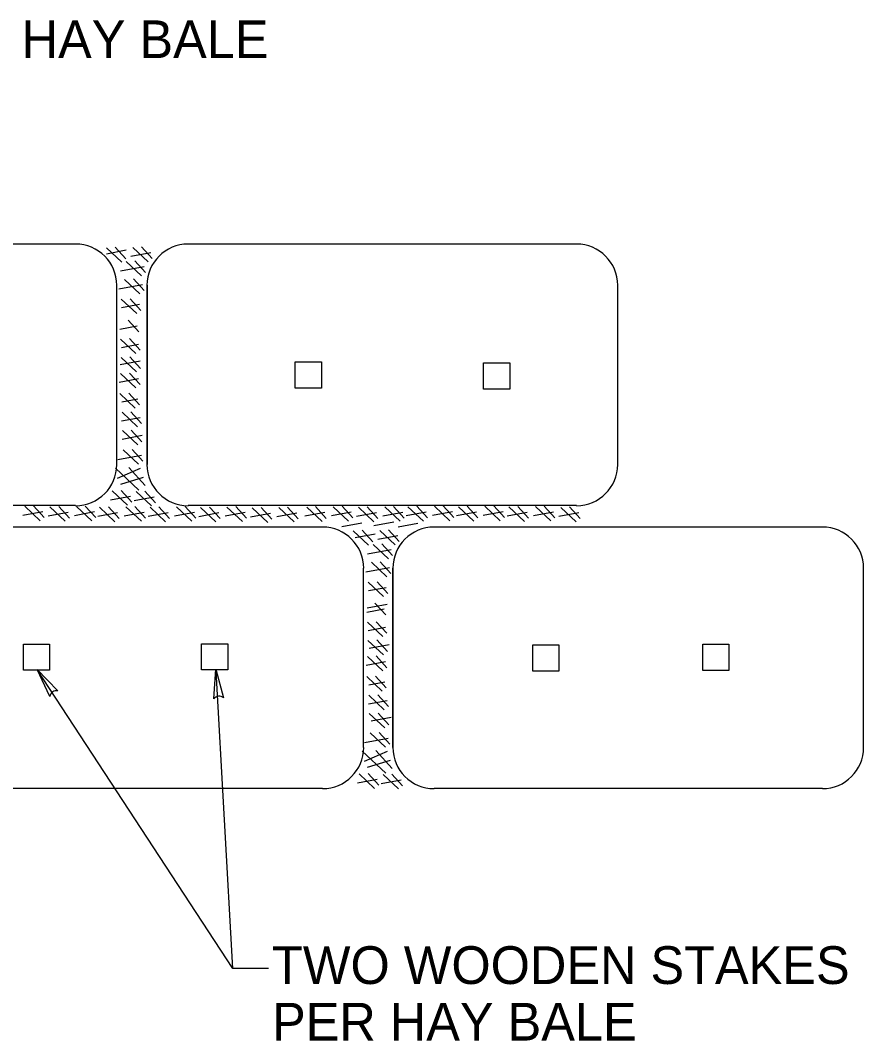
# Model space of a CAD drawing. Extents: x 0 to 2.83, y -0.06 to 1.83.
# Drawn here: x 2.1578 to 2.3533, y 0.8651 to 1.1016 of the extents above; entities that cross this region are included whole.
import ezdxf

# ---------------------------------------------------------------- set-up
doc = ezdxf.new("R2010")
doc.units = 0
for name, color, linetype in [('Edge_of_Truck_Apron', 7, 'Continuous'), ('Haybales', 7, 'Continuous'), ('Longitudinal Joint', 7, 'Continuous'), ('Wood Stakes', 7, 'Continuous')]:
    doc.layers.add(name, color=color, linetype=linetype)

msp = doc.modelspace()

# ---------------------------------------------------------------- linework, layer by layer
at = {"layer": 'Edge_of_Truck_Apron'}
for p, q in [((2.20708, 0.88183), (2.16174, 0.95101)), ((2.20708, 0.88183), (2.20318, 0.95078)), ((2.21533, 0.88183), (2.20708, 0.88183))]:
    msp.add_line(p, q, dxfattribs=at)
at = {"layer": 'Haybales'}
for p, q in [((2.17059, 1.04975), (2.08056, 1.04975)), ((2.17059, 1.04975), (2.08056, 1.04975)), ((2.17773, 1.04889), (2.1813, 1.04555)), ((2.17773, 1.04889), (2.1813, 1.04555)), ((2.18236, 1.04831), (2.17773, 1.04745)), ((2.18236, 1.04831), (2.17773, 1.04745)), ((2.17978, 1.04901), (2.18226, 1.0463)), ((2.17978, 1.04901), (2.18226, 1.0463)), ((2.18806, 1.04772), (2.18343, 1.04686)), ((2.18806, 1.04772), (2.18343, 1.04686)), ((2.18386, 1.04899), (2.18742, 1.04565)), ((2.18386, 1.04899), (2.18742, 1.04565)), ((2.18591, 1.0491), (2.18839, 1.0464)), ((2.18591, 1.0491), (2.18839, 1.0464)), ((2.28673, 1.04975), (2.1967, 1.04975)), ((2.28673, 1.04975), (2.1967, 1.04975)), ((2.1823, 1.04575), (2.18587, 1.04241)), ((2.1823, 1.04575), (2.18587, 1.04241)), ((2.18436, 1.04586), (2.18683, 1.04316)), ((2.18436, 1.04586), (2.18683, 1.04316)), ((2.1865, 1.04448), (2.18102, 1.04346)), ((2.1865, 1.04448), (2.18102, 1.04346)), ((2.18194, 1.04158), (2.18551, 1.03824)), ((2.18194, 1.04158), (2.18551, 1.03824)), ((2.18399, 1.04169), (2.18647, 1.03899)), ((2.18399, 1.04169), (2.18647, 1.03899)), ((2.18014, 0.99867), (2.18014, 1.0402)), ((2.18014, 0.99867), (2.18014, 1.0402)), ((2.18614, 1.04031), (2.18065, 1.03929)), ((2.18614, 1.04031), (2.18065, 1.03929)), ((2.18716, 1.0402), (2.18716, 0.99867)), ((2.18716, 0.99867), (2.18716, 1.0402)), ((2.18716, 1.0402), (2.18716, 0.99867)), ((2.18716, 0.99867), (2.18716, 1.0402)), ((2.29628, 0.99867), (2.29628, 1.0402)), ((2.29628, 0.99867), (2.29628, 1.0402)), ((2.1812, 1.03699), (2.18477, 1.03364)), ((2.1812, 1.03699), (2.18477, 1.03364)), ((2.18325, 1.0371), (2.18573, 1.03439)), ((2.18325, 1.0371), (2.18573, 1.03439)), ((2.1854, 1.03571), (2.18128, 1.03495)), ((2.1854, 1.03571), (2.18128, 1.03495)), ((2.18277, 1.03211), (2.18524, 1.02941)), ((2.18277, 1.03211), (2.18524, 1.02941)), ((2.18491, 1.03073), (2.18089, 1.02998)), ((2.18491, 1.03073), (2.18089, 1.02998)), ((2.18101, 1.02772), (2.18458, 1.02438)), ((2.18101, 1.02772), (2.18458, 1.02438)), ((2.18521, 1.02645), (2.18121, 1.02571)), ((2.18521, 1.02645), (2.18121, 1.02571)), ((2.18306, 1.02783), (2.18554, 1.02513)), ((2.18306, 1.02783), (2.18554, 1.02513)), ((2.18554, 1.02262), (2.18091, 1.02176)), ((2.18554, 1.02262), (2.18091, 1.02176)), ((2.18115, 1.0235), (2.18471, 1.02015)), ((2.18115, 1.0235), (2.18471, 1.02015)), ((2.1832, 1.02361), (2.18568, 1.0209)), ((2.1832, 1.02361), (2.18568, 1.0209)), ((2.18102, 1.01976), (2.18458, 1.01642)), ((2.18102, 1.01976), (2.18458, 1.01642)), ((2.18307, 1.01987), (2.18555, 1.01717)), ((2.18307, 1.01987), (2.18555, 1.01717)), ((2.18522, 1.01849), (2.18071, 1.01766)), ((2.18522, 1.01849), (2.18071, 1.01766)), ((2.18086, 1.01509), (2.18443, 1.01174)), ((2.18086, 1.01509), (2.18443, 1.01174)), ((2.18291, 1.0152), (2.18539, 1.01249)), ((2.18291, 1.0152), (2.18539, 1.01249)), ((2.18506, 1.01381), (2.18133, 1.01312)), ((2.18506, 1.01381), (2.18133, 1.01312)), ((2.18136, 1.01076), (2.18492, 1.00741)), ((2.18136, 1.01076), (2.18492, 1.00741)), ((2.18341, 1.01087), (2.18589, 1.00816)), ((2.18341, 1.01087), (2.18589, 1.00816)), ((2.18555, 1.00948), (2.18126, 1.00869)), ((2.18555, 1.00948), (2.18126, 1.00869)), ((2.18601, 1.00535), (2.18139, 1.00449)), ((2.18601, 1.00535), (2.18139, 1.00449)), ((2.18145, 1.00654), (2.18501, 1.0032)), ((2.18145, 1.00654), (2.18501, 1.0032)), ((2.1835, 1.00665), (2.18598, 1.00395)), ((2.1835, 1.00665), (2.18598, 1.00395)), ((2.18585, 1.00078), (2.18037, 0.99976)), ((2.18585, 1.00078), (2.18037, 0.99976)), ((2.18166, 1.00205), (2.18522, 0.99871)), ((2.18166, 1.00205), (2.18522, 0.99871)), ((2.18371, 1.00216), (2.18618, 0.99946)), ((2.18371, 1.00216), (2.18618, 0.99946)), ((2.18296, 0.99795), (2.18673, 0.99383)), ((2.18296, 0.99795), (2.18673, 0.99383)), ((2.17983, 0.99778), (2.18527, 0.99268)), ((2.17983, 0.99778), (2.18527, 0.99268)), ((2.18557, 0.99775), (2.18025, 0.99542)), ((2.18557, 0.99775), (2.18025, 0.99542)), ((2.18106, 0.99411), (2.18638, 0.99573)), ((2.18106, 0.99411), (2.18638, 0.99573)), ((2.1833, 0.99127), (2.17868, 0.99041)), ((2.1833, 0.99127), (2.17868, 0.99041)), ((2.17911, 0.99254), (2.18267, 0.9892)), ((2.17911, 0.99254), (2.18267, 0.9892)), ((2.18116, 0.99266), (2.18363, 0.98995)), ((2.18116, 0.99266), (2.18363, 0.98995)), ((2.18882, 0.99112), (2.1842, 0.99026)), ((2.18882, 0.99112), (2.1842, 0.99026)), ((2.18463, 0.99239), (2.18819, 0.98905)), ((2.18463, 0.99239), (2.18819, 0.98905)), ((2.18668, 0.9925), (2.18915, 0.9898)), ((2.18668, 0.9925), (2.18915, 0.9898)), ((2.15882, 0.98897), (2.16238, 0.98563)), ((2.15882, 0.98897), (2.16238, 0.98563)), ((2.16087, 0.98908), (2.16335, 0.98638)), ((2.16087, 0.98908), (2.16335, 0.98638)), ((2.16465, 0.98883), (2.16822, 0.98549)), ((2.16465, 0.98883), (2.16822, 0.98549)), ((2.16671, 0.98895), (2.16918, 0.98624)), ((2.16671, 0.98895), (2.16918, 0.98624)), ((2.17078, 0.98893), (2.17435, 0.98559)), ((2.17078, 0.98893), (2.17435, 0.98559)), ((2.17283, 0.98904), (2.17531, 0.98634)), ((2.17283, 0.98904), (2.17531, 0.98634)), ((2.17615, 0.98875), (2.17972, 0.9854)), ((2.17615, 0.98875), (2.17972, 0.9854)), ((2.1782, 0.98886), (2.18068, 0.98615)), ((2.1782, 0.98886), (2.18068, 0.98615)), ((2.18228, 0.98885), (2.18585, 0.9855)), ((2.18228, 0.98885), (2.18585, 0.9855)), ((2.18433, 0.98896), (2.18681, 0.98625)), ((2.18433, 0.98896), (2.18681, 0.98625)), ((2.18786, 0.98875), (2.19143, 0.98541)), ((2.18786, 0.98875), (2.19143, 0.98541)), ((2.18991, 0.98886), (2.19239, 0.98616)), ((2.18991, 0.98886), (2.19239, 0.98616)), ((2.19399, 0.98885), (2.19755, 0.9855)), ((2.19399, 0.98885), (2.19755, 0.9855)), ((2.19604, 0.98896), (2.19851, 0.98625)), ((2.19604, 0.98896), (2.19851, 0.98625)), ((2.19957, 0.9887), (2.20313, 0.98536)), ((2.19957, 0.9887), (2.20313, 0.98536)), ((2.20162, 0.98881), (2.2041, 0.98611)), ((2.20162, 0.98881), (2.2041, 0.98611)), ((2.2057, 0.9888), (2.20926, 0.98545)), ((2.2057, 0.9888), (2.20926, 0.98545)), ((2.20775, 0.98891), (2.21022, 0.9862)), ((2.20775, 0.98891), (2.21022, 0.9862)), ((2.21157, 0.9886), (2.21513, 0.98525)), ((2.21157, 0.9886), (2.21513, 0.98525)), ((2.21362, 0.98871), (2.2161, 0.986)), ((2.21362, 0.98871), (2.2161, 0.986)), ((2.2177, 0.9887), (2.22126, 0.98535)), ((2.2177, 0.9887), (2.22126, 0.98535)), ((2.21975, 0.98881), (2.22222, 0.9861)), ((2.21975, 0.98881), (2.22222, 0.9861)), ((2.22419, 0.98878), (2.22776, 0.98543)), ((2.22419, 0.98878), (2.22776, 0.98543)), ((2.22624, 0.98889), (2.22872, 0.98618)), ((2.22624, 0.98889), (2.22872, 0.98618)), ((2.23032, 0.98887), (2.23388, 0.98553)), ((2.23032, 0.98887), (2.23388, 0.98553)), ((2.23237, 0.98898), (2.23484, 0.98628)), ((2.23237, 0.98898), (2.23484, 0.98628)), ((2.23615, 0.98874), (2.23972, 0.98539)), ((2.23615, 0.98874), (2.23972, 0.98539)), ((2.2382, 0.98885), (2.24068, 0.98614)), ((2.2382, 0.98885), (2.24068, 0.98614)), ((2.24228, 0.98883), (2.24585, 0.98549)), ((2.24228, 0.98883), (2.24585, 0.98549)), ((2.24433, 0.98895), (2.24681, 0.98624)), ((2.24433, 0.98895), (2.24681, 0.98624)), ((2.24766, 0.98888), (2.25122, 0.98553)), ((2.24766, 0.98888), (2.25122, 0.98553)), ((2.24971, 0.98899), (2.25218, 0.98628)), ((2.24971, 0.98899), (2.25218, 0.98628)), ((2.25378, 0.98897), (2.25735, 0.98563)), ((2.25378, 0.98897), (2.25735, 0.98563)), ((2.25583, 0.98908), (2.25831, 0.98638)), ((2.25583, 0.98908), (2.25831, 0.98638)), ((2.25936, 0.98888), (2.26293, 0.98553)), ((2.25936, 0.98888), (2.26293, 0.98553)), ((2.26141, 0.98899), (2.26389, 0.98628)), ((2.26141, 0.98899), (2.26389, 0.98628)), ((2.26549, 0.98897), (2.26906, 0.98563)), ((2.26549, 0.98897), (2.26906, 0.98563)), ((2.26754, 0.98909), (2.27002, 0.98638)), ((2.26754, 0.98909), (2.27002, 0.98638)), ((2.27107, 0.98883), (2.27464, 0.98548)), ((2.27107, 0.98883), (2.27464, 0.98548)), ((2.27312, 0.98894), (2.2756, 0.98623)), ((2.27312, 0.98894), (2.2756, 0.98623)), ((2.2772, 0.98893), (2.28076, 0.98558)), ((2.2772, 0.98893), (2.28076, 0.98558)), ((2.27925, 0.98904), (2.28173, 0.98633)), ((2.27925, 0.98904), (2.28173, 0.98633)), ((2.28307, 0.98873), (2.28664, 0.98538)), ((2.28307, 0.98873), (2.28664, 0.98538)), ((2.28512, 0.98884), (2.2876, 0.98613)), ((2.28512, 0.98884), (2.2876, 0.98613)), ((2.16301, 0.9877), (2.15839, 0.98684)), ((2.16301, 0.9877), (2.15839, 0.98684)), ((2.16885, 0.98756), (2.16422, 0.9867)), ((2.16885, 0.98756), (2.16422, 0.9867)), ((2.17498, 0.98766), (2.17035, 0.9868)), ((2.17498, 0.98766), (2.17035, 0.9868)), ((2.18035, 0.98747), (2.17572, 0.98662)), ((2.18035, 0.98747), (2.17572, 0.98662)), ((2.18648, 0.98757), (2.18185, 0.98671)), ((2.18648, 0.98757), (2.18185, 0.98671)), ((2.19206, 0.98747), (2.18743, 0.98662)), ((2.19206, 0.98747), (2.18743, 0.98662)), ((2.19818, 0.98757), (2.19355, 0.98672)), ((2.19818, 0.98757), (2.19355, 0.98672)), ((2.20377, 0.98743), (2.19914, 0.98657)), ((2.20377, 0.98743), (2.19914, 0.98657)), ((2.20989, 0.98752), (2.20526, 0.98667)), ((2.20989, 0.98752), (2.20526, 0.98667)), ((2.21577, 0.98732), (2.21114, 0.98647)), ((2.21577, 0.98732), (2.21114, 0.98647)), ((2.22189, 0.98742), (2.21726, 0.98656)), ((2.22189, 0.98742), (2.21726, 0.98656)), ((2.22839, 0.9875), (2.22376, 0.98665)), ((2.22839, 0.9875), (2.22376, 0.98665)), ((2.23451, 0.9876), (2.22989, 0.98674)), ((2.23451, 0.9876), (2.22989, 0.98674)), ((2.24035, 0.98746), (2.23572, 0.98661)), ((2.24035, 0.98746), (2.23572, 0.98661)), ((2.24648, 0.98756), (2.24185, 0.9867)), ((2.24648, 0.98756), (2.24185, 0.9867)), ((2.25185, 0.9876), (2.24723, 0.98675)), ((2.25185, 0.9876), (2.24723, 0.98675)), ((2.25798, 0.9877), (2.25335, 0.98684)), ((2.25798, 0.9877), (2.25335, 0.98684)), ((2.26356, 0.9876), (2.25893, 0.98675)), ((2.26356, 0.9876), (2.25893, 0.98675)), ((2.26969, 0.9877), (2.26506, 0.98684)), ((2.26969, 0.9877), (2.26506, 0.98684)), ((2.27527, 0.98755), (2.27064, 0.9867)), ((2.27527, 0.98755), (2.27064, 0.9867)), ((2.2814, 0.98765), (2.27677, 0.9868)), ((2.2814, 0.98765), (2.27677, 0.9868)), ((2.28727, 0.98745), (2.28264, 0.9866)), ((2.28727, 0.98745), (2.28264, 0.9866)), ((2.23696, 0.98504), (2.23233, 0.98418)), ((2.23696, 0.98504), (2.23233, 0.98418)), ((2.2444, 0.98532), (2.23978, 0.98447)), ((2.2444, 0.98532), (2.23978, 0.98447)), ((2.24998, 0.98501), (2.24535, 0.98415)), ((2.24998, 0.98501), (2.24535, 0.98415)), ((2.34374, 0.98416), (2.25371, 0.98416)), ((2.34374, 0.98416), (2.25371, 0.98416)), ((2.23497, 0.9833), (2.23854, 0.97995)), ((2.23497, 0.9833), (2.23854, 0.97995)), ((2.24004, 0.98252), (2.23541, 0.98166)), ((2.24004, 0.98252), (2.23541, 0.98166)), ((2.23702, 0.98341), (2.2395, 0.9807)), ((2.23702, 0.98341), (2.2395, 0.9807)), ((2.2453, 0.98212), (2.24067, 0.98126)), ((2.2453, 0.98212), (2.24067, 0.98126)), ((2.2411, 0.98339), (2.24467, 0.98005)), ((2.2411, 0.98339), (2.24467, 0.98005)), ((2.24315, 0.9835), (2.24563, 0.9808)), ((2.24315, 0.9835), (2.24563, 0.9808)), ((2.23955, 0.98015), (2.24311, 0.97681)), ((2.23955, 0.98015), (2.24311, 0.97681)), ((2.2416, 0.98026), (2.24407, 0.97756)), ((2.2416, 0.98026), (2.24407, 0.97756)), ((2.24374, 0.97888), (2.23826, 0.97786)), ((2.24374, 0.97888), (2.23826, 0.97786)), ((2.23738, 0.93308), (2.23738, 0.97461)), ((2.23738, 0.93308), (2.23738, 0.97461)), ((2.24338, 0.97471), (2.23789, 0.9737)), ((2.24338, 0.97471), (2.23789, 0.9737)), ((2.23918, 0.97599), (2.24275, 0.97264)), ((2.23918, 0.97599), (2.24275, 0.97264)), ((2.24123, 0.9761), (2.24371, 0.97339)), ((2.24123, 0.9761), (2.24371, 0.97339)), ((2.24417, 0.93308), (2.24417, 0.97461)), ((2.24417, 0.97461), (2.24417, 0.93308)), ((2.24417, 0.93308), (2.24417, 0.97461)), ((2.24417, 0.93308), (2.24417, 0.97461)), ((2.24417, 0.97461), (2.24417, 0.93308)), ((2.24417, 0.93308), (2.24417, 0.97461)), ((2.35329, 0.93308), (2.35329, 0.97461)), ((2.35329, 0.93308), (2.35329, 0.97461)), ((2.23844, 0.97139), (2.24201, 0.96804)), ((2.23844, 0.97139), (2.24201, 0.96804)), ((2.24264, 0.97011), (2.23852, 0.96935)), ((2.24264, 0.97011), (2.23852, 0.96935)), ((2.24049, 0.9715), (2.24297, 0.96879)), ((2.24049, 0.9715), (2.24297, 0.96879)), ((2.24216, 0.96513), (2.23813, 0.96438)), ((2.24216, 0.96513), (2.23813, 0.96438)), ((2.24285, 0.96625), (2.23822, 0.9654)), ((2.24285, 0.96625), (2.23822, 0.9654)), ((2.24001, 0.96651), (2.24249, 0.96381)), ((2.24001, 0.96651), (2.24249, 0.96381)), ((2.23825, 0.96212), (2.24182, 0.95878)), ((2.23825, 0.96212), (2.24182, 0.95878)), ((2.24245, 0.96085), (2.23845, 0.96011)), ((2.24245, 0.96085), (2.23845, 0.96011)), ((2.2403, 0.96223), (2.24278, 0.95953)), ((2.2403, 0.96223), (2.24278, 0.95953)), ((2.23839, 0.9579), (2.24196, 0.95455)), ((2.23839, 0.9579), (2.24196, 0.95455)), ((2.24044, 0.95801), (2.24292, 0.9553)), ((2.24044, 0.95801), (2.24292, 0.9553)), ((2.24331, 0.95689), (2.23868, 0.95604)), ((2.24331, 0.95689), (2.23868, 0.95604)), ((2.23826, 0.95417), (2.24183, 0.95082)), ((2.23826, 0.95417), (2.24183, 0.95082)), ((2.24031, 0.95428), (2.24279, 0.95157)), ((2.24031, 0.95428), (2.24279, 0.95157)), ((2.16464, 0.94491), (2.16168, 0.95111)), ((2.16168, 0.95111), (2.16649, 0.9462)), ((2.16464, 0.94491), (2.16168, 0.95111)), ((2.16168, 0.95111), (2.16649, 0.9462)), ((2.20264, 0.94433), (2.2031, 0.95119)), ((2.20264, 0.94433), (2.2031, 0.95119)), ((2.2031, 0.95119), (2.20489, 0.94455)), ((2.2031, 0.95119), (2.20489, 0.94455)), ((2.24246, 0.95289), (2.23795, 0.95206)), ((2.24246, 0.95289), (2.23795, 0.95206)), ((2.2381, 0.94949), (2.24167, 0.94614)), ((2.2381, 0.94949), (2.24167, 0.94614)), ((2.24015, 0.9496), (2.24263, 0.94689)), ((2.24015, 0.9496), (2.24263, 0.94689)), ((2.2423, 0.94821), (2.23858, 0.94752)), ((2.2423, 0.94821), (2.23858, 0.94752)), ((2.2428, 0.94389), (2.2385, 0.94309)), ((2.2428, 0.94389), (2.2385, 0.94309)), ((2.2386, 0.94516), (2.24216, 0.94182)), ((2.2386, 0.94516), (2.24216, 0.94182)), ((2.24065, 0.94527), (2.24313, 0.94257)), ((2.24065, 0.94527), (2.24313, 0.94257)), ((2.23869, 0.94094), (2.24226, 0.9376)), ((2.23869, 0.94094), (2.24226, 0.9376)), ((2.24375, 0.94004), (2.23912, 0.93919)), ((2.24375, 0.94004), (2.23912, 0.93919)), ((2.24074, 0.94105), (2.24322, 0.93835)), ((2.24074, 0.94105), (2.24322, 0.93835)), ((2.2389, 0.93646), (2.24246, 0.93311)), ((2.2389, 0.93646), (2.24246, 0.93311)), ((2.24095, 0.93657), (2.24343, 0.93386)), ((2.24095, 0.93657), (2.24343, 0.93386)), ((2.2431, 0.93518), (2.23761, 0.93417)), ((2.2431, 0.93518), (2.23761, 0.93417)), ((2.23707, 0.93218), (2.24251, 0.92709)), ((2.23707, 0.93218), (2.24251, 0.92709)), ((2.24281, 0.93216), (2.23749, 0.92983)), ((2.24281, 0.93216), (2.23749, 0.92983)), ((2.2402, 0.93235), (2.24397, 0.92823)), ((2.2402, 0.93235), (2.24397, 0.92823)), ((2.2383, 0.92851), (2.24362, 0.93013)), ((2.2383, 0.92851), (2.24362, 0.93013)), ((2.2384, 0.92706), (2.24088, 0.92435)), ((2.2384, 0.92706), (2.24088, 0.92435)), ((2.24055, 0.92567), (2.23592, 0.92482)), ((2.24055, 0.92567), (2.23592, 0.92482)), ((2.23635, 0.92695), (2.23991, 0.9236)), ((2.23635, 0.92695), (2.23991, 0.9236)), ((2.24607, 0.92552), (2.24144, 0.92466)), ((2.24607, 0.92552), (2.24144, 0.92466)), ((2.24187, 0.9268), (2.24543, 0.92345)), ((2.24187, 0.9268), (2.24543, 0.92345)), ((2.24392, 0.92691), (2.2464, 0.9242)), ((2.24392, 0.92691), (2.2464, 0.9242))]:
    msp.add_line(p, q, dxfattribs=at)
for points in [[(2.22758, 1.01638), (2.22151, 1.01638), (2.22151, 1.02244), (2.22758, 1.02244)], [(2.2652, 1.01615), (2.2652, 1.02221), (2.27126, 1.02221), (2.27126, 1.01615)], [(2.16457, 0.95099), (2.15851, 0.95099), (2.15851, 0.95705), (2.16457, 0.95705)], [(2.19982, 0.95107), (2.19982, 0.95713), (2.20588, 0.95713), (2.20588, 0.95107)], [(2.28263, 0.95077), (2.27657, 0.95077), (2.27657, 0.95683), (2.28263, 0.95683)], [(2.31602, 0.95094), (2.31602, 0.95701), (2.32208, 0.95701), (2.32208, 0.95094)]]:
    msp.add_lwpolyline(points, close=True, dxfattribs=at)
for points in [[(2.17059, 0.98913), (2.08056, 0.98913)], [(2.17059, 0.98913), (2.08056, 0.98913)], [(2.28673, 0.98913), (2.1967, 0.98913)], [(2.28673, 0.98913), (2.1967, 0.98913)], [(2.22784, 0.98416), (2.13781, 0.98416)], [(2.22784, 0.98416), (2.13781, 0.98416)], [(2.22784, 0.92354), (2.13781, 0.92354)], [(2.22784, 0.92354), (2.13781, 0.92354)], [(2.34374, 0.92354), (2.25371, 0.92354)], [(2.34374, 0.92354), (2.25371, 0.92354)]]:
    msp.add_lwpolyline(points, dxfattribs=at)
for centre, radius, start, end in [((2.17059, 1.0402), 0.00955, 360, 90), ((2.17059, 1.0402), 0.00955, 360, 90), ((2.1967, 1.0402), 0.00955, 90, 180), ((2.1967, 1.0402), 0.00955, 90, 180), ((2.28673, 1.0402), 0.00955, 360, 90), ((2.28673, 1.0402), 0.00955, 360, 90), ((2.17059, 0.99867), 0.00955, 270, 360), ((2.17059, 0.99867), 0.00955, 270, 360), ((2.1967, 0.99867), 0.00955, 180, 270), ((2.1967, 0.99867), 0.00955, 180, 270), ((2.28673, 0.99867), 0.00955, 270, 360), ((2.28673, 0.99867), 0.00955, 270, 360), ((2.22784, 0.97461), 0.00955, 360, 90), ((2.22784, 0.97461), 0.00955, 360, 90), ((2.25371, 0.97461), 0.00955, 90, 180), ((2.25371, 0.97461), 0.00955, 90, 180), ((2.34374, 0.97461), 0.00955, 360, 90), ((2.34374, 0.97461), 0.00955, 360, 90), ((2.16617, 0.94469), 0.00154, 77.9045, 171.9692), ((2.16617, 0.94469), 0.00154, 77.9045, 171.9692), ((2.20387, 0.9434), 0.00154, 48.5445, 142.6092), ((2.20387, 0.9434), 0.00154, 48.5445, 142.6092), ((2.22784, 0.93308), 0.00955, 270, 360), ((2.22784, 0.93308), 0.00955, 270, 360), ((2.25371, 0.93308), 0.00955, 180, 270), ((2.25371, 0.93308), 0.00955, 180, 270), ((2.34374, 0.93308), 0.00955, 270, 360), ((2.34374, 0.93308), 0.00955, 270, 360)]:
    msp.add_arc(centre, radius, start, end, dxfattribs=at)
at = {"layer": 'Longitudinal Joint'}
for p, q in [((2.20708, 0.88183), (2.16174, 0.95101)), ((2.20708, 0.88183), (2.20318, 0.95078)), ((2.21533, 0.88183), (2.20708, 0.88183))]:
    msp.add_line(p, q, dxfattribs=at)
at = {"layer": 'Wood Stakes'}
for points in [[(2.22758, 1.01638), (2.22151, 1.01638), (2.22151, 1.02244), (2.22758, 1.02244)], [(2.2652, 1.01615), (2.2652, 1.02221), (2.27126, 1.02221), (2.27126, 1.01615)], [(2.16457, 0.95099), (2.15851, 0.95099), (2.15851, 0.95705), (2.16457, 0.95705)], [(2.19982, 0.95107), (2.19982, 0.95713), (2.20588, 0.95713), (2.20588, 0.95107)], [(2.28263, 0.95077), (2.27657, 0.95077), (2.27657, 0.95683), (2.28263, 0.95683)], [(2.31602, 0.95094), (2.31602, 0.95701), (2.32208, 0.95701), (2.32208, 0.95094)]]:
    msp.add_lwpolyline(points, close=True, dxfattribs=at)

# ---------------------------------------------------------------- texts
at = {"layer": 'Edge_of_Truck_Apron'}
for s, p in [('HAY BALE', (2.15809, 1.09285)), ('TWO WOODEN STAKES ', (2.21614, 0.87825)), ('PER HAY BALE', (2.21614, 0.86513))]:
    msp.add_text(s, height=0.00875, dxfattribs=at).set_placement(p)

doc.saveas('drawing.dxf')
